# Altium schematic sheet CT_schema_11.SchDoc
size 146 x 119 mm
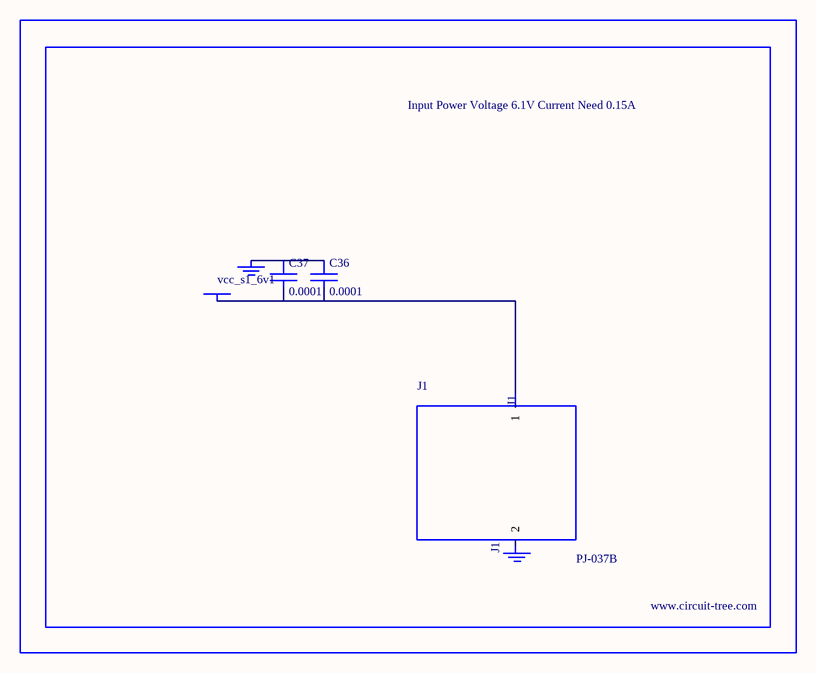
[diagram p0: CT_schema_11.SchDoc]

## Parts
BORDER10  (no value)
C36  0.0001  [EXV-9H]
C37  0.0001  [EXV-9H]
GND_INSTANCE_10_0  (no value)
GND_INSTANCE_10_1  (no value)
J1  PJ-037B  [PJ-037B_PACKAGE]
POWER_INSTANCE_10_0  vcc_s1_6v1

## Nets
NetC36_1: C36.1 C37.1 GND_INSTANCE_10_0.0(GND)
NetC36_2: C36.2 C37.2 J1.1 POWER_INSTANCE_10_0.0(PWR)

Not connected (* = marked no-connect by the designer): GND_INSTANCE_10_1 0(GND); J1 2

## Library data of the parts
BORDER10 = BORDER_PAGE10
C36 C37 = EDK107M035A9HAA
GND_INSTANCE_10_0 GND_INSTANCE_10_1 = GND
POWER_INSTANCE_10_0 = PWR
